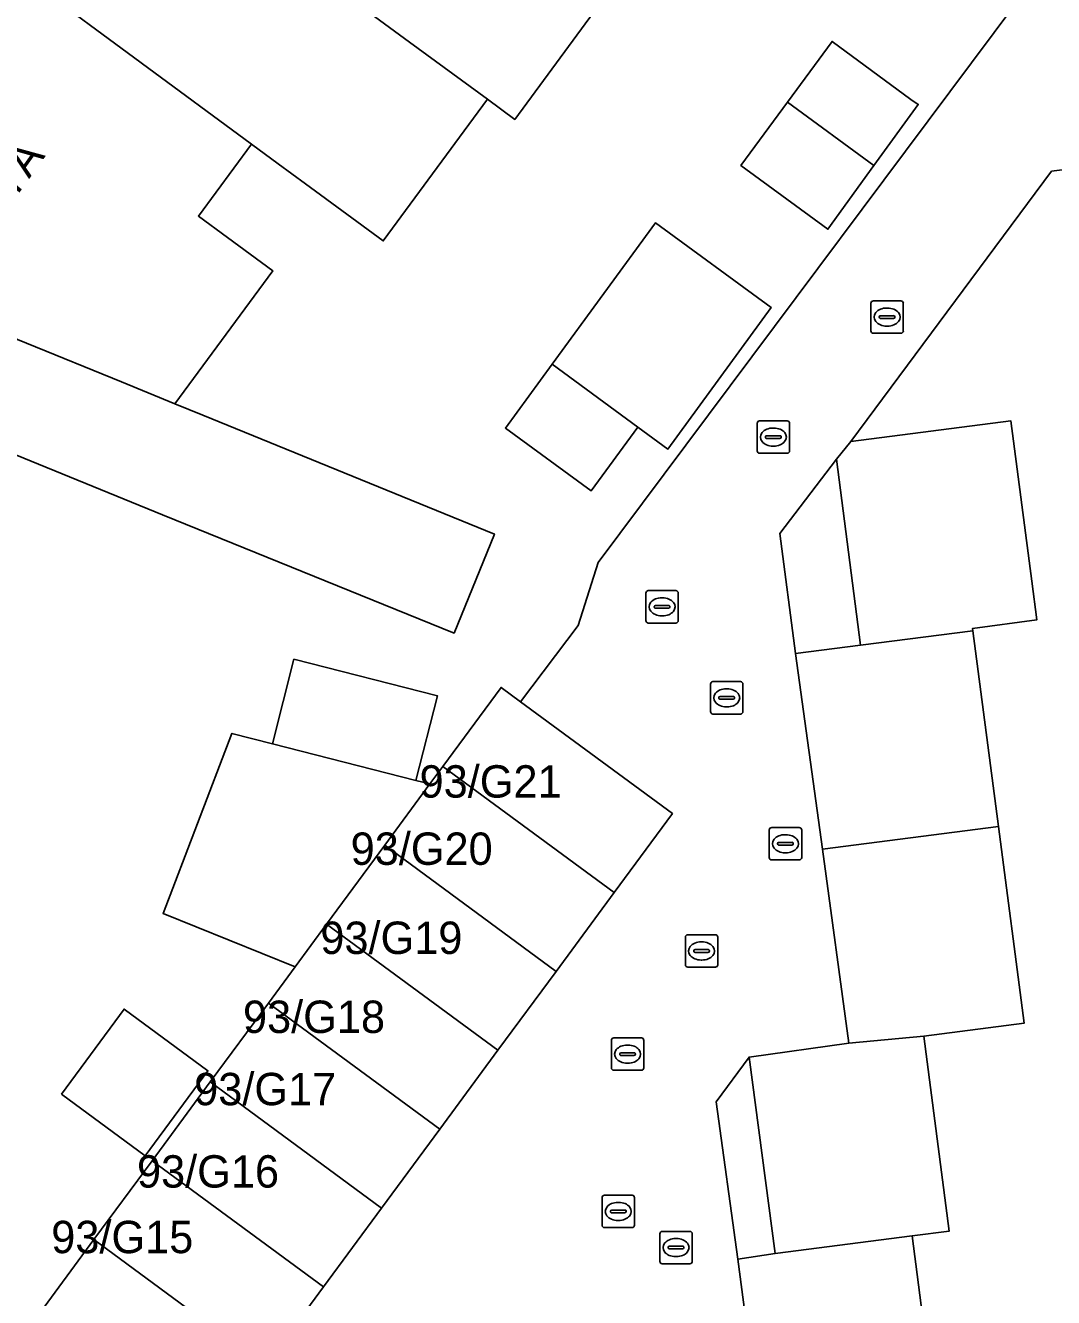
# Model space of a CAD drawing. Extents: x 160554 to 161248, y 385329 to 386506.
# Drawn here: x 161018.73 to 161050.48, y 386001.11 to 386040.42 of the extents above; entities that cross this region are included whole.
import ezdxf

# ---------------------------------------------------------------- set-up
doc = ezdxf.new("R2010")
doc.units = 0
for name, color, linetype in [('IMGEO_Erf', 7, 'Continuous'), ('IMGEO_Kolk', 7, 'Continuous'), ('IMGEO_Pand', 7, 'Continuous'), ('IMGEO_Pand_nummerreeks', 7, 'Continuous'), ('IMGEO_Rijbaan_lokaal_open', 7, 'Continuous'), ('IMGEO_Rioolput', 7, 'Continuous'), ('IMGEO_Voetpad_open', 7, 'Continuous')]:
    doc.layers.add(name, color=color, linetype=linetype)

msp = doc.modelspace()

# ---------------------------------------------------------------- linework, layer by layer
at = {"layer": 'IMGEO_Erf'}
for points in [[(161019.051, 386000.465), (161020.847, 386002.903), (161022.643, 386005.34), (161024.439, 386007.777), (161026.235, 386010.214), (161027.062, 386011.336), (161022.984, 386012.983), (161025.107, 386018.546), (161026.357, 386018.226), (161027.023, 386020.836), (161031.454, 386019.707), (161030.788, 386017.094), (161031.223, 386016.983), (161031.623, 386017.526), (161033.419, 386019.964), (161034.022, 386019.52), (161035.801, 386021.883), (161036.421, 386023.828), (161051.352, 386043.836)], [(161037.049, 386041.881), (161033.843, 386037.518), (161032.998, 386038.14), (161032.422, 386037.356), (161029.781, 386033.762), (161027.38, 386035.527), (161026.535, 386036.148), (161025.71, 386036.754), (161024.073, 386034.527), (161024.976, 386033.864), (161026.37, 386032.841), (161023.35, 386028.728), (161024.21, 386028.377), (161033.212, 386024.706), (161031.969, 386021.643), (161022.962, 386025.303), (161017.939, 386027.344)], [(161051.828, 386036.088), (161050.417, 386035.918), (161044.224, 386027.561), (161049.157, 386028.206), (161049.807, 386023.249), (161049.963, 386022.049), (161047.98, 386021.79), (161047.99, 386021.71), (161048.781, 386015.666), (161049.575, 386009.594), (161046.472, 386009.189), (161047.26, 386003.165), (161046.109, 386003.017), (161046.901, 385996.967), (161047.692, 385990.916), (161048.495, 385984.776), (161054.445, 385985.554)]]:
    msp.add_lwpolyline(points, dxfattribs=at)
for points in [[(161042.263, 386038.051), (161043.641, 386039.926), (161046.077, 386038.136), (161046.304, 386037.981), (161044.934, 386036.088), (161043.51, 386034.12), (161040.824, 386036.093)], [(161038.192, 386034.324), (161041.76, 386031.702), (161038.57, 386027.328), (161037.641, 386028.011), (161036.202, 386026.041), (161033.552, 386027.978), (161034.997, 386029.954)], [(161043.777, 386027.018), (161042.028, 386024.721), (161042.516, 386021.012), (161044.516, 386021.267)], [(161019.845, 386007.402), (161021.778, 386010.025), (161024.365, 386008.119), (161022.431, 386005.496)]]:
    msp.add_lwpolyline(points, close=True, dxfattribs=at)
at = {"layer": 'IMGEO_Kolk'}
for p, q in [((161041.327, 386027.275), (161041.327, 386028.127)), ((161041.402, 386028.201), (161042.254, 386028.201)), ((161041.815, 386027.981), (161041.84, 386027.981)), ((161042.328, 386028.127), (161042.328, 386027.275)), ((161041.586, 386027.695), (161041.586, 386027.707)), ((161042.024, 386027.658), (161041.626, 386027.658)), ((161041.629, 386027.744), (161042.027, 386027.744)), ((161042.07, 386027.707), (161042.07, 386027.695)), ((161042.254, 386027.201), (161041.402, 386027.201)), ((161041.838, 386027.421), (161041.813, 386027.421)), ((161039.886, 386019.218), (161039.886, 386020.07)), ((161039.961, 386020.144), (161040.813, 386020.144)), ((161040.887, 386020.07), (161040.887, 386019.218)), ((161040.145, 386019.638), (161040.145, 386019.65)), ((161040.583, 386019.601), (161040.185, 386019.601)), ((161040.188, 386019.687), (161040.586, 386019.687)), ((161040.374, 386019.924), (161040.399, 386019.924)), ((161040.629, 386019.65), (161040.629, 386019.638)), ((161040.397, 386019.364), (161040.372, 386019.364)), ((161040.813, 386019.144), (161039.961, 386019.144)), ((161039.11, 386011.397), (161039.11, 386012.249)), ((161039.185, 386012.323), (161040.037, 386012.323)), ((161040.111, 386012.249), (161040.111, 386011.397)), ((161039.369, 386011.817), (161039.369, 386011.829)), ((161039.807, 386011.78), (161039.409, 386011.78)), ((161039.412, 386011.866), (161039.81, 386011.866)), ((161039.598, 386012.103), (161039.623, 386012.103)), ((161039.853, 386011.829), (161039.853, 386011.817)), ((161039.621, 386011.543), (161039.596, 386011.543)), ((161040.037, 386011.323), (161039.185, 386011.323)), ((161036.614, 386004.275), (161037.466, 386004.275)), ((161036.539, 386003.349), (161036.539, 386004.201)), ((161037.027, 386004.055), (161037.052, 386004.055)), ((161037.54, 386004.201), (161037.54, 386003.349)), ((161036.798, 386003.769), (161036.798, 386003.781)), ((161037.236, 386003.732), (161036.838, 386003.732)), ((161036.841, 386003.818), (161037.239, 386003.818)), ((161037.05, 386003.495), (161037.025, 386003.495)), ((161037.282, 386003.781), (161037.282, 386003.769)), ((161037.466, 386003.275), (161036.614, 386003.275))]:
    msp.add_line(p, q, dxfattribs=at)
for points in [[(161041.327, 386027.275), (161041.327, 386028.127)], [(161041.402, 386028.201), (161042.254, 386028.201)], [(161042.328, 386028.127), (161042.328, 386027.275)], [(161042.254, 386027.201), (161041.402, 386027.201)], [(161039.886, 386019.218), (161039.886, 386020.07)], [(161039.961, 386020.144), (161040.813, 386020.144)], [(161040.887, 386020.07), (161040.887, 386019.218)], [(161040.813, 386019.144), (161039.961, 386019.144)], [(161039.11, 386011.397), (161039.11, 386012.249)], [(161039.185, 386012.323), (161040.037, 386012.323)], [(161040.111, 386012.249), (161040.111, 386011.397)], [(161040.037, 386011.323), (161039.185, 386011.323)], [(161036.614, 386004.275), (161037.466, 386004.275)], [(161036.539, 386003.349), (161036.539, 386004.201)], [(161037.54, 386004.201), (161037.54, 386003.349)], [(161037.466, 386003.275), (161036.614, 386003.275)]]:
    msp.add_lwpolyline(points, dxfattribs=at)
for centre, radius, start, end in [((161041.404, 386028.125), 0.0765, 91.552, 178.448), ((161041.404, 386028.125), 0.0765, 91.552, 178.448), ((161042.252, 386028.125), 0.0765, 1.552, 88.448), ((161042.252, 386028.125), 0.0765, 1.552, 88.448), ((161041.626, 386027.704), 0.0403, 85.8775, 175.7526), ((161041.623, 386027.694), 0.0366, 178.938, 274.7102), ((161042.027, 386027.701), 0.043, 264.8664, 352.4533), ((161042.031, 386027.706), 0.0386, 1.7309, 96.639), ((161041.404, 386027.277), 0.0765, 181.552, 268.448), ((161041.404, 386027.277), 0.0765, 181.552, 268.448), ((161042.252, 386027.277), 0.0765, 271.552, 358.448), ((161042.252, 386027.277), 0.0765, 271.552, 358.448), ((161039.963, 386020.068), 0.0765, 91.552, 178.448), ((161039.963, 386020.068), 0.0765, 91.552, 178.448), ((161040.811, 386020.068), 0.0765, 1.552, 88.448), ((161040.811, 386020.068), 0.0765, 1.552, 88.448), ((161040.185, 386019.647), 0.0403, 85.8775, 175.7526), ((161040.182, 386019.637), 0.0366, 178.938, 274.7102), ((161040.586, 386019.644), 0.043, 264.8664, 352.4533), ((161040.59, 386019.649), 0.0386, 1.7309, 96.639), ((161039.963, 386019.22), 0.0765, 181.552, 268.448), ((161039.963, 386019.22), 0.0765, 181.552, 268.448), ((161040.811, 386019.22), 0.0765, 271.552, 358.448), ((161040.811, 386019.22), 0.0765, 271.552, 358.448), ((161039.187, 386012.247), 0.0765, 91.552, 178.448), ((161039.187, 386012.247), 0.0765, 91.552, 178.448), ((161040.035, 386012.247), 0.0765, 1.552, 88.448), ((161040.035, 386012.247), 0.0765, 1.552, 88.448), ((161039.409, 386011.826), 0.0403, 85.8775, 175.7526), ((161039.406, 386011.816), 0.0366, 178.938, 274.7102), ((161039.81, 386011.823), 0.043, 264.8664, 352.4533), ((161039.814, 386011.828), 0.0386, 1.7309, 96.639), ((161039.187, 386011.399), 0.0765, 181.552, 268.448), ((161039.187, 386011.399), 0.0765, 181.552, 268.448), ((161040.035, 386011.399), 0.0765, 271.552, 358.448), ((161040.035, 386011.399), 0.0765, 271.552, 358.448), ((161036.616, 386004.199), 0.0765, 91.552, 178.448), ((161036.616, 386004.199), 0.0765, 91.552, 178.448), ((161037.464, 386004.199), 0.0765, 1.552, 88.448), ((161037.464, 386004.199), 0.0765, 1.552, 88.448), ((161036.838, 386003.778), 0.0403, 85.8775, 175.7526), ((161036.835, 386003.768), 0.0366, 178.938, 274.7102), ((161037.239, 386003.775), 0.043, 264.8664, 352.4533), ((161037.243, 386003.78), 0.0386, 1.7309, 96.639), ((161036.616, 386003.351), 0.0765, 181.552, 268.448), ((161036.616, 386003.351), 0.0765, 181.552, 268.448), ((161037.464, 386003.351), 0.0765, 271.552, 358.448), ((161037.464, 386003.351), 0.0765, 271.552, 358.448)]:
    msp.add_arc(centre, radius, start, end, dxfattribs=at)
for centre, major_axis, ratio, start_param, end_param in [((161041.814, 386027.701), (-0.387, 0.002), 0.722429, 4.712389, 7.853982), ((161041.839, 386027.701), (-0.39, 0.002), 0.717154, 1.570796, 4.712389), ((161040.373, 386019.644), (-0.387, 0.002), 0.722429, 4.712389, 7.853982), ((161040.398, 386019.644), (-0.39, 0.002), 0.717154, 1.570796, 4.712389), ((161039.597, 386011.823), (-0.387, 0.002), 0.722429, 4.712389, 7.853982), ((161039.622, 386011.823), (-0.39, 0.002), 0.717154, 1.570796, 4.712389), ((161037.026, 386003.775), (-0.387, 0.002), 0.722429, 4.712389, 7.853982), ((161037.051, 386003.775), (-0.39, 0.002), 0.717154, 1.570796, 4.712389)]:
    msp.add_ellipse(centre, major_axis=major_axis, ratio=ratio, start_param=start_param, end_param=end_param, dxfattribs=at)
at = {"layer": 'IMGEO_Pand'}
for points in [[(161025.306, 386050.509), (161022.101, 386046.148), (161030.597, 386039.904), (161032.998, 386038.14), (161033.843, 386037.518), (161037.049, 386041.881), (161033.803, 386044.266)], [(161022.101, 386046.148), (161018.894, 386041.785), (161025.71, 386036.754), (161026.535, 386036.148), (161027.38, 386035.527), (161029.781, 386033.762), (161032.422, 386037.356), (161032.998, 386038.14), (161030.597, 386039.904)], [(161025.71, 386036.754), (161018.894, 386041.785), (161015.583, 386037.279), (161015.833, 386037.096), (161012.89, 386032.99), (161021.697, 386029.403), (161023.35, 386028.728), (161026.37, 386032.841), (161024.976, 386033.864), (161024.073, 386034.527)], [(161046.077, 386038.136), (161043.641, 386039.926), (161042.263, 386038.051), (161044.934, 386036.088), (161046.304, 386037.981)], [(161042.263, 386038.051), (161040.824, 386036.093), (161043.51, 386034.12), (161044.934, 386036.088)], [(161041.76, 386031.702), (161038.192, 386034.324), (161034.997, 386029.954), (161037.641, 386028.011), (161038.57, 386027.328)], [(161024.21, 386028.377), (161023.35, 386028.728), (161021.697, 386029.403), (161012.89, 386032.99), (161011.65, 386033.496), (161007.646, 386027.97), (161012.275, 386026.078), (161016.685, 386024.276), (161017.939, 386027.344), (161022.962, 386025.303), (161031.969, 386021.643), (161033.212, 386024.706)], [(161034.997, 386029.954), (161033.552, 386027.978), (161036.202, 386026.041), (161037.641, 386028.011)], [(161049.157, 386028.206), (161044.224, 386027.561), (161043.777, 386027.018), (161044.516, 386021.267), (161047.99, 386021.71), (161047.98, 386021.79), (161049.963, 386022.049), (161049.807, 386023.249)], [(161047.99, 386021.71), (161044.516, 386021.267), (161042.516, 386021.012), (161043.341, 386014.966), (161048.781, 386015.666)], [(161026.357, 386018.226), (161030.788, 386017.094), (161031.454, 386019.707), (161027.023, 386020.836)], [(161038.709, 386016.065), (161034.022, 386019.52), (161033.419, 386019.964), (161031.623, 386017.526), (161036.913, 386013.628)], [(161031.223, 386016.983), (161030.788, 386017.094), (161026.357, 386018.226), (161025.107, 386018.546), (161022.984, 386012.983), (161027.062, 386011.336), (161028.031, 386012.652), (161029.827, 386015.089)], [(161031.623, 386017.526), (161031.223, 386016.983), (161029.827, 386015.089), (161035.117, 386011.191), (161036.913, 386013.628)], [(161044.158, 386008.974), (161046.472, 386009.189), (161049.575, 386009.594), (161048.781, 386015.666), (161043.341, 386014.966)], [(161035.117, 386011.191), (161029.827, 386015.089), (161028.031, 386012.652), (161033.321, 386008.753)], [(161028.031, 386012.652), (161027.062, 386011.336), (161026.235, 386010.214), (161031.525, 386006.316), (161033.321, 386008.753)], [(161031.525, 386006.316), (161026.235, 386010.214), (161024.439, 386007.777), (161029.729, 386003.879)], [(161019.845, 386007.402), (161022.431, 386005.496), (161024.365, 386008.119), (161021.778, 386010.025)], [(161046.472, 386009.189), (161044.158, 386008.974), (161041.078, 386008.543), (161041.881, 386002.473), (161046.109, 386003.017), (161047.26, 386003.165)], [(161029.729, 386003.879), (161024.439, 386007.777), (161022.643, 386005.34), (161027.933, 386001.442)], [(161026.871, 386000), (161027.933, 386001.442), (161022.643, 386005.34), (161020.847, 386002.903), (161026.137, 385999.004)], [(161026.137, 385999.004), (161020.847, 386002.903), (161019.051, 386000.465), (161024.341, 385996.567)], [(161046.109, 386003.017), (161041.881, 386002.473), (161040.729, 386002.303), (161041.525, 385996.276), (161046.901, 385996.967)]]:
    msp.add_lwpolyline(points, close=True, dxfattribs=at)
at = {"layer": 'IMGEO_Rijbaan_lokaal_open'}
for points in [[(161051.352, 386043.836), (161036.421, 386023.828), (161035.801, 386021.883), (161034.022, 386019.52), (161038.709, 386016.065), (161036.913, 386013.628), (161035.117, 386011.191), (161033.321, 386008.753), (161031.525, 386006.316), (161029.729, 386003.879), (161027.933, 386001.442), (161026.871, 386000), (161026.137, 385999.004), (161024.341, 385996.567), (161022.545, 385994.13), (161020.75, 385991.692), (161018.954, 385989.255), (161017.158, 385986.818), (161015.362, 385984.381), (161013.566, 385981.943), (161011.77, 385979.506), (161019.362, 385975.725), (161032.442, 385996.293), (161034.254, 385999.08)], [(161042.516, 386021.012), (161042.028, 386024.721), (161043.777, 386027.018), (161044.224, 386027.561), (161050.417, 386035.918), (161051.828, 386036.088)], [(161048.827, 385974.296), (161049.696, 385978.869), (161049.946, 385980.185), (161046.119, 385980.889), (161043.5, 385981.394), (161043.151, 385983.98), (161042.325, 385990.226), (161041.525, 385996.276), (161040.729, 386002.303), (161040.06, 386007.157), (161041.078, 386008.543), (161044.158, 386008.974), (161043.341, 386014.966), (161042.516, 386021.012)]]:
    msp.add_lwpolyline(points, dxfattribs=at)
at = {"layer": 'IMGEO_Rioolput'}
for p, q in [((161044.84, 386030.983), (161044.84, 386031.835)), ((161044.915, 386031.909), (161045.767, 386031.909)), ((161045.841, 386031.835), (161045.841, 386030.983)), ((161045.099, 386031.403), (161045.099, 386031.415)), ((161045.142, 386031.452), (161045.54, 386031.452)), ((161045.328, 386031.689), (161045.353, 386031.689)), ((161045.583, 386031.415), (161045.583, 386031.403)), ((161045.537, 386031.366), (161045.139, 386031.366)), ((161045.351, 386031.129), (161045.326, 386031.129)), ((161045.767, 386030.909), (161044.915, 386030.909)), ((161037.891, 386022.03), (161037.891, 386022.882)), ((161037.966, 386022.956), (161038.818, 386022.956)), ((161038.379, 386022.736), (161038.404, 386022.736)), ((161038.892, 386022.882), (161038.892, 386022.03)), ((161038.15, 386022.45), (161038.15, 386022.462)), ((161038.588, 386022.413), (161038.19, 386022.413)), ((161038.193, 386022.499), (161038.591, 386022.499)), ((161038.634, 386022.462), (161038.634, 386022.45)), ((161038.818, 386021.956), (161037.966, 386021.956)), ((161038.402, 386022.176), (161038.377, 386022.176)), ((161041.701, 386014.71), (161041.701, 386015.562)), ((161041.776, 386015.636), (161042.628, 386015.636)), ((161042.189, 386015.416), (161042.214, 386015.416)), ((161042.702, 386015.562), (161042.702, 386014.71)), ((161041.96, 386015.13), (161041.96, 386015.142)), ((161042.398, 386015.093), (161042, 386015.093)), ((161042.003, 386015.179), (161042.401, 386015.179)), ((161042.444, 386015.142), (161042.444, 386015.13)), ((161042.628, 386014.636), (161041.776, 386014.636)), ((161042.212, 386014.856), (161042.187, 386014.856)), ((161036.826, 386008.209), (161036.826, 386009.061)), ((161036.901, 386009.135), (161037.753, 386009.135)), ((161037.827, 386009.061), (161037.827, 386008.209)), ((161037.085, 386008.629), (161037.085, 386008.641)), ((161037.523, 386008.592), (161037.125, 386008.592)), ((161037.128, 386008.678), (161037.526, 386008.678)), ((161037.314, 386008.915), (161037.339, 386008.915)), ((161037.569, 386008.641), (161037.569, 386008.629)), ((161037.337, 386008.355), (161037.312, 386008.355)), ((161037.753, 386008.135), (161036.901, 386008.135)), ((161038.321, 386002.232), (161038.321, 386003.084)), ((161038.396, 386003.158), (161039.248, 386003.158)), ((161039.322, 386003.084), (161039.322, 386002.232)), ((161038.623, 386002.701), (161039.021, 386002.701)), ((161038.809, 386002.938), (161038.834, 386002.938)), ((161038.58, 386002.652), (161038.58, 386002.664)), ((161039.018, 386002.615), (161038.62, 386002.615)), ((161038.832, 386002.378), (161038.807, 386002.378)), ((161039.064, 386002.664), (161039.064, 386002.652)), ((161039.248, 386002.158), (161038.396, 386002.158))]:
    msp.add_line(p, q, dxfattribs=at)
for points in [[(161044.84, 386030.983), (161044.84, 386031.835)], [(161044.915, 386031.909), (161045.767, 386031.909)], [(161045.841, 386031.835), (161045.841, 386030.983)], [(161045.767, 386030.909), (161044.915, 386030.909)], [(161037.891, 386022.03), (161037.891, 386022.882)], [(161037.966, 386022.956), (161038.818, 386022.956)], [(161038.892, 386022.882), (161038.892, 386022.03)], [(161038.818, 386021.956), (161037.966, 386021.956)], [(161041.701, 386014.71), (161041.701, 386015.562)], [(161041.776, 386015.636), (161042.628, 386015.636)], [(161042.702, 386015.562), (161042.702, 386014.71)], [(161042.628, 386014.636), (161041.776, 386014.636)], [(161036.826, 386008.209), (161036.826, 386009.061)], [(161036.901, 386009.135), (161037.753, 386009.135)], [(161037.827, 386009.061), (161037.827, 386008.209)], [(161037.753, 386008.135), (161036.901, 386008.135)], [(161038.321, 386002.232), (161038.321, 386003.084)], [(161038.396, 386003.158), (161039.248, 386003.158)], [(161039.322, 386003.084), (161039.322, 386002.232)], [(161039.248, 386002.158), (161038.396, 386002.158)]]:
    msp.add_lwpolyline(points, dxfattribs=at)
for centre, radius, start, end in [((161044.917, 386031.833), 0.0765, 91.552, 178.448), ((161044.917, 386031.833), 0.0765, 91.552, 178.448), ((161045.765, 386031.833), 0.0765, 1.552, 88.448), ((161045.765, 386031.833), 0.0765, 1.552, 88.448), ((161045.139, 386031.412), 0.0403, 85.8775, 175.7526), ((161045.136, 386031.402), 0.0366, 178.938, 274.7102), ((161045.54, 386031.409), 0.043, 264.8664, 352.4533), ((161045.544, 386031.414), 0.0386, 1.7309, 96.639), ((161044.917, 386030.985), 0.0765, 181.552, 268.448), ((161044.917, 386030.985), 0.0765, 181.552, 268.448), ((161045.765, 386030.985), 0.0765, 271.552, 358.448), ((161045.765, 386030.985), 0.0765, 271.552, 358.448), ((161037.968, 386022.88), 0.0765, 91.552, 178.448), ((161037.968, 386022.88), 0.0765, 91.552, 178.448), ((161038.816, 386022.88), 0.0765, 1.552, 88.448), ((161038.816, 386022.88), 0.0765, 1.552, 88.448), ((161038.19, 386022.459), 0.0403, 85.8775, 175.7526), ((161038.187, 386022.449), 0.0366, 178.938, 274.7102), ((161038.591, 386022.456), 0.043, 264.8664, 352.4533), ((161038.595, 386022.461), 0.0386, 1.7309, 96.639), ((161037.968, 386022.032), 0.0765, 181.552, 268.448), ((161037.968, 386022.032), 0.0765, 181.552, 268.448), ((161038.816, 386022.032), 0.0765, 271.552, 358.448), ((161038.816, 386022.032), 0.0765, 271.552, 358.448), ((161041.778, 386015.56), 0.0765, 91.552, 178.448), ((161041.778, 386015.56), 0.0765, 91.552, 178.448), ((161042.626, 386015.56), 0.0765, 1.552, 88.448), ((161042.626, 386015.56), 0.0765, 1.552, 88.448), ((161042, 386015.139), 0.0403, 85.8775, 175.7526), ((161041.997, 386015.129), 0.0366, 178.938, 274.7102), ((161042.401, 386015.136), 0.043, 264.8664, 352.4533), ((161042.405, 386015.141), 0.0386, 1.7309, 96.639), ((161041.778, 386014.712), 0.0765, 181.552, 268.448), ((161041.778, 386014.712), 0.0765, 181.552, 268.448), ((161042.626, 386014.712), 0.0765, 271.552, 358.448), ((161042.626, 386014.712), 0.0765, 271.552, 358.448), ((161036.903, 386009.059), 0.0765, 91.552, 178.448), ((161036.903, 386009.059), 0.0765, 91.552, 178.448), ((161037.751, 386009.059), 0.0765, 1.552, 88.448), ((161037.751, 386009.059), 0.0765, 1.552, 88.448), ((161037.125, 386008.638), 0.0403, 85.8775, 175.7526), ((161037.122, 386008.628), 0.0366, 178.938, 274.7102), ((161037.526, 386008.635), 0.043, 264.8664, 352.4533), ((161037.53, 386008.64), 0.0386, 1.7309, 96.639), ((161036.903, 386008.211), 0.0765, 181.552, 268.448), ((161036.903, 386008.211), 0.0765, 181.552, 268.448), ((161037.751, 386008.211), 0.0765, 271.552, 358.448), ((161037.751, 386008.211), 0.0765, 271.552, 358.448), ((161038.398, 386003.082), 0.0765, 91.552, 178.448), ((161038.398, 386003.082), 0.0765, 91.552, 178.448), ((161039.246, 386003.082), 0.0765, 1.552, 88.448), ((161039.246, 386003.082), 0.0765, 1.552, 88.448), ((161038.62, 386002.661), 0.0403, 85.8775, 175.7526), ((161039.025, 386002.663), 0.0386, 1.7309, 96.639), ((161038.617, 386002.651), 0.0366, 178.938, 274.7102), ((161039.021, 386002.658), 0.043, 264.8664, 352.4533), ((161038.398, 386002.234), 0.0765, 181.552, 268.448), ((161038.398, 386002.234), 0.0765, 181.552, 268.448), ((161039.246, 386002.234), 0.0765, 271.552, 358.448), ((161039.246, 386002.234), 0.0765, 271.552, 358.448)]:
    msp.add_arc(centre, radius, start, end, dxfattribs=at)
for centre, major_axis, ratio, start_param, end_param in [((161045.327, 386031.409), (-0.387, 0.002), 0.722429, 4.712389, 7.853982), ((161045.352, 386031.409), (-0.39, 0.002), 0.717154, 1.570796, 4.712389), ((161038.378, 386022.456), (-0.387, 0.002), 0.722429, 4.712389, 7.853982), ((161038.403, 386022.456), (-0.39, 0.002), 0.717154, 1.570796, 4.712389), ((161042.188, 386015.136), (-0.387, 0.002), 0.722429, 4.712389, 7.853982), ((161042.213, 386015.136), (-0.39, 0.002), 0.717154, 1.570796, 4.712389), ((161037.313, 386008.635), (-0.387, 0.002), 0.722429, 4.712389, 7.853982), ((161037.338, 386008.635), (-0.39, 0.002), 0.717154, 1.570796, 4.712389), ((161038.808, 386002.658), (-0.387, 0.002), 0.722429, 4.712389, 7.853982), ((161038.833, 386002.658), (-0.39, 0.002), 0.717154, 1.570796, 4.712389)]:
    msp.add_ellipse(centre, major_axis=major_axis, ratio=ratio, start_param=start_param, end_param=end_param, dxfattribs=at)
at = {"layer": 'IMGEO_Voetpad_open'}
msp.add_lwpolyline([(161041.078, 386008.543), (161040.06, 386007.157), (161040.729, 386002.303), (161041.881, 386002.473)], close=True, dxfattribs=at)

# ---------------------------------------------------------------- texts
at = {"layer": 'IMGEO_Pand_nummerreeks'}
msp.add_text('287A', height=1, rotation=54.368, dxfattribs=at).set_placement((161017.544, 386033.855))
for s, p in [('93/G21', (161030.903, 386016.561)), ('93/G20', (161028.774, 386014.483)), ('93/G19', (161027.839, 386011.73)), ('93/G18', (161025.45, 386009.289)), ('93/G17', (161023.943, 386007.056)), ('93/G16', (161022.177, 386004.511)), ('93/G15', (161019.529, 386002.485))]:
    msp.add_text(s, height=1, dxfattribs=at).set_placement(p)

doc.saveas('drawing.dxf')
